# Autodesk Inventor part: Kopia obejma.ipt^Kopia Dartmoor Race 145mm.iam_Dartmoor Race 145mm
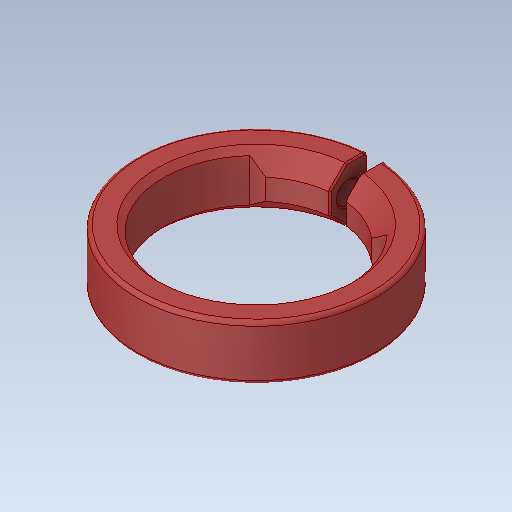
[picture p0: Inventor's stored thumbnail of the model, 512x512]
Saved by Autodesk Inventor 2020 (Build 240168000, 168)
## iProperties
Created: 2017-10
Part Number: Kopia obejma.ipt^Kopia Dartmoor Race 145mm.iam_Dartmoor Race 145mm
Material: Ogólny
Document SubType Name: Modeling
Designer: Tomasz
Density: 1 g/cm^3
Appearance: Domyślna
Sending System: SolidWorks 2017
Last Author: Tomasz
Last Saved: 2017-10-01
Author: Tomasz
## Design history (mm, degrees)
feature "obejma.ipt"
node "Bryła1"
